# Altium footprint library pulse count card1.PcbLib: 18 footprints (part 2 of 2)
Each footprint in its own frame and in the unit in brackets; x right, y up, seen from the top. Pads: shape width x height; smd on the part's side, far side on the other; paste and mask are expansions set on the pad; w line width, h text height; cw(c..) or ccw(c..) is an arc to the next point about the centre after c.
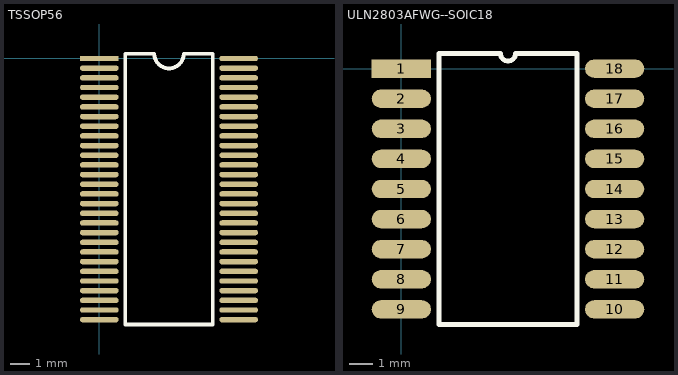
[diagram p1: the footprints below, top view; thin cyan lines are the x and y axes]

## TSSOP56 [mm]
pads (56):
  rect 2x0.28 smd: 1(-0.003,-0.01)
  oval 2x0.28 smd: 2(-0.003,-0.51) 3(-0.003,-1.01) 4(-0.003,-1.51) 5(-0.003,-2.01) 6(-0.003,-2.51) 7(-0.003,-3.01) 8(-0.003,-3.51) 9(-0.003,-4.01) 10(-0.003,-4.51) 11(-0.003,-5.01) 12(-0.003,-5.51) 13(-0.003,-6.01) 14(-0.003,-6.51) 15(-0.003,-7.01) 16(-0.003,-7.51) 17(-0.003,-8.01) 18(-0.003,-8.51) 19(-0.003,-9.01) 20(-0.003,-9.51) 21(-0.003,-10.01) 22(-0.003,-10.51) 23(-0.003,-11.01) 24(-0.003,-11.51) 25(-0.003,-12.01) 26(-0.003,-12.51) 27(-0.003,-13.01) 28(-0.003,-13.51) 29(7.197,-13.51) 30(7.197,-13.01) 31(7.197,-12.51) 32(7.197,-12.01) 33(7.197,-11.51) 34(7.197,-11.01) 35(7.197,-10.51) 36(7.197,-10.01) 37(7.197,-9.51) 38(7.197,-9.01) 39(7.197,-8.51) 40(7.197,-8.01) 41(7.197,-7.51) 42(7.197,-7.01) 43(7.197,-6.51) 44(7.197,-6.01) 45(7.197,-5.51) 46(7.197,-5.01) 47(7.197,-4.51) 48(7.197,-4.01) 49(7.197,-3.51) 50(7.197,-3.01) 51(7.197,-2.51) 52(7.197,-2.01) 53(7.197,-1.51) 54(7.197,-1.01) 55(7.197,-0.51) 56(7.197,-0.01)
Top Overlay:
  lines w0.2: 1.332,-13.76 1.332,0.24 2.838,0.24 ccw(c3.597,0.24) 4.357,0.24 5.862,0.24 5.862,-13.76 1.332,-13.76

## ULN2803AFWG--SOIC18 [mm]
pads (18):
  rect 2.5x0.773 smd: 1(0,0)
  oval 2.5x0.773 smd: 2(0,-1.27) 3(0,-2.54) 4(0,-3.81) 5(0,-5.08) 6(0,-6.35) 7(0,-7.62) 8(0,-8.89) 9(0,-10.16) 10(9,-10.16) 11(9,-8.89) 12(9,-7.62) 13(9,-6.35) 14(9,-5.08) 15(9,-3.81) 16(9,-2.54) 17(9,-1.27) 18(9,0)
Top Overlay:
  lines w0.2: 1.585,-10.795 7.415,-10.795 7.415,0.635 4.817,0.635 cw(c4.5,0.635) 4.182,0.635 1.585,0.635 1.585,-10.795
